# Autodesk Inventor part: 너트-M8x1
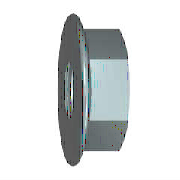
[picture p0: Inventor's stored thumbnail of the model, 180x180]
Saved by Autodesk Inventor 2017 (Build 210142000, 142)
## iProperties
Created: 2015-12
Part Number: 너트-M8x1
Material: 스테인리스강
Description: 플랜지붙이 6각 너트 - 일반 스레드
Document SubType Name: Modeling
Standard: ISO 4161
Designer: mdu
Standard Revision: 2판 1999-03-15
Standards Organization: ISO
Language: ko-KR
Size Designation: M8
Categories: <MemberInstance><Categories><Category DisplayName="조임쇠" InternalName="e4da775c-781d-43d5-af7c-5136215cf5a6" Mnemonic="FSTN"><Category DisplayName="너트" InternalN
Density: 8.08 g/cm^3
Appearance: 강철
Author: mdu
IsCustomPart: 1
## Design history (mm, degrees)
sketch "스케치1"
  geometry: L1 (-1.844, 0)-(9.641, 0) reference; L2 (3.107, 6.5)-(2.288, 8.257); L3 (3.107, 6.5)-(8, 6.5); L4 (8, 6.5)-(8, 0); L5 (3.107, 6.5)-(3.107, 0); L6 (0, -1.835)-(0, 11.01) reference; A1 r 1.2 centre (1.2, 7.75) between (2.288, 8.257) and (0, 7.75); 1 further point
  constraints: 8 end point, 3 point on line, 2 perpendicular, 2 point on circle, 2 tangent, 1 centre point, 1 parallel
  dimensions: "d2" = 13 diameter of L3 L1 (= SW); "d4" = 17.9 dimension on A1 L1 (= LADI); "d5" = 1.2 radius of A1 (= PHH); "d15" = 8 distance between parallel lines of L4 L6 (= KOH); "d16" = 25 deg angle of L6 L2 (= KEWI)
revolve "링" sketch "스케치1" stored, may be unused: angle "d8" = 90 deg
sketch "스케치2"
  geometry: L1 (-6.5, -3.753)-(-6.5, 3.753); L2 (-6.5, 3.753)-(0, 7.506); L3 (0, 7.506)-(6.5, 3.753); L4 (6.5, 3.753)-(6.5, -3.753); L5 (6.5, -3.753)-(0, -7.506); L6 (0, -7.506)-(-6.5, -3.753); C1 r 4.9 at (0, 0); C2 r 7.75 at (0, 0) reference; 1 further point
  constraints: 12 end point, 1 centre point, 1 coincident, 1 vertical, 11 other
  dimensions: "d6" = 15.01111 distance of L5.end L2.end (= 1.1547 x SW)
extrude "본체" join sketch "스케치2" distance "d7" = 8 (= KOH); taper "d9" = 0 deg
sketch "스케치3"
  geometry: L1 (2.638, 7.506)-(8, 7.506) reference; L2 (8, 3.753)-(8, 7.506) reference; L3 (0, -7.75)-(0, 7.75) reference; L4 (-1.6, 0)-(9.6, 0) reference; L5 (7.419, 7.506)-(8, 6.5)
  constraints: 2 end point, 2 point on line
  dimensions: "d10" = 30 deg angle of L2 L5 (= ANG1); "d11" = 13 diameter of L5.end L4 (= SW0)
revolve "모따기1" sketch "스케치3" stored, may be unused: angle "d24" = 90 deg
sketch "스케치4"
  geometry: C1 r 7.75 at (0, 0) reference; 1 further point
  constraints: 1 coincident
hole "스레드" sketch "스케치4" at (0, 0) diameter "d25" = 6.647; stored, may be unused: countersink angle "d29" = 82 deg, drill point angle "d31" = 118 deg; dims "d26" = 6, "d27" = 4, "d28" = 2, "d30" = 8
workaxis "Work Axis1"
workplane "Work Plane1"
body "Solid1"
chamfer "모따기2" distance "d12" = 0.67658 (= -0.5 x GD1 + 0.5 x NND); stored, may be unused: angle "d13" = 30 deg, second distance "d46" = 0.67658 (= -0.5 x GD1 + 0.5 x NND)
chamfer "모따기3" distance "d51" = 0.67658 (= -0.5 x GD1 + 0.5 x NND); stored, may be unused: second distance "d52" = 2, angle "d53" = 45 deg
other parameters: "ANG1" = 30 deg [user parameter; used in 1 equation term], "KEWI" = 25 deg [user parameter; used in 1 equation term], "NND" = 8 [user parameter; used in 4 equation terms], "LADI" = 17.9 [user parameter; used in 2 equation terms], "SW" = 13 [user parameter; used in 3 equation terms], "PHH" = 1.2 [user parameter; used in 3 equation terms], "KOH" = 8 (= NND) [user parameter; used in 2 equation terms], "SW0" = 13 [user parameter; used in 1 equation term], "GD1" = 6.64684 (computed from THREADDIA, PTC, TOA) [user parameter; used in 3 equation terms], "d1" = 17.9 (= LADI), "d3" = 1.2 (= PHH), "d45" = 0, "d47" = 0, "d49" = 0, "d54" = 0, "GUL" = 0.67658 (= 0.541266 x PTC) [user parameter], "TPU" = 8 (computed from PTC) [user parameter], "RR" = 1.2 (= PHH) [user parameter], "THREADDIA" = 8 [user parameter; used in 1 equation term], "TOA" = 30 deg [user parameter; used in 1 equation term], "PTC" = 1.25 [user parameter; used in 4 equation terms], "GAL" = 0.67658 (= 0.541266 x PTC) [user parameter], "E0" = 15.015 (= 1.155 x SW) [user parameter]
